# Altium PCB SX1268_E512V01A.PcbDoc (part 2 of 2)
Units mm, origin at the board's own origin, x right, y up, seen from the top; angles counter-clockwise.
Board outline 89 x 58 mm, 2 copper layers (Top Layer, Bottom Layer), stack 0.22 mm thick; 87 components, 53 nets, 246 pads, 1394 vias.
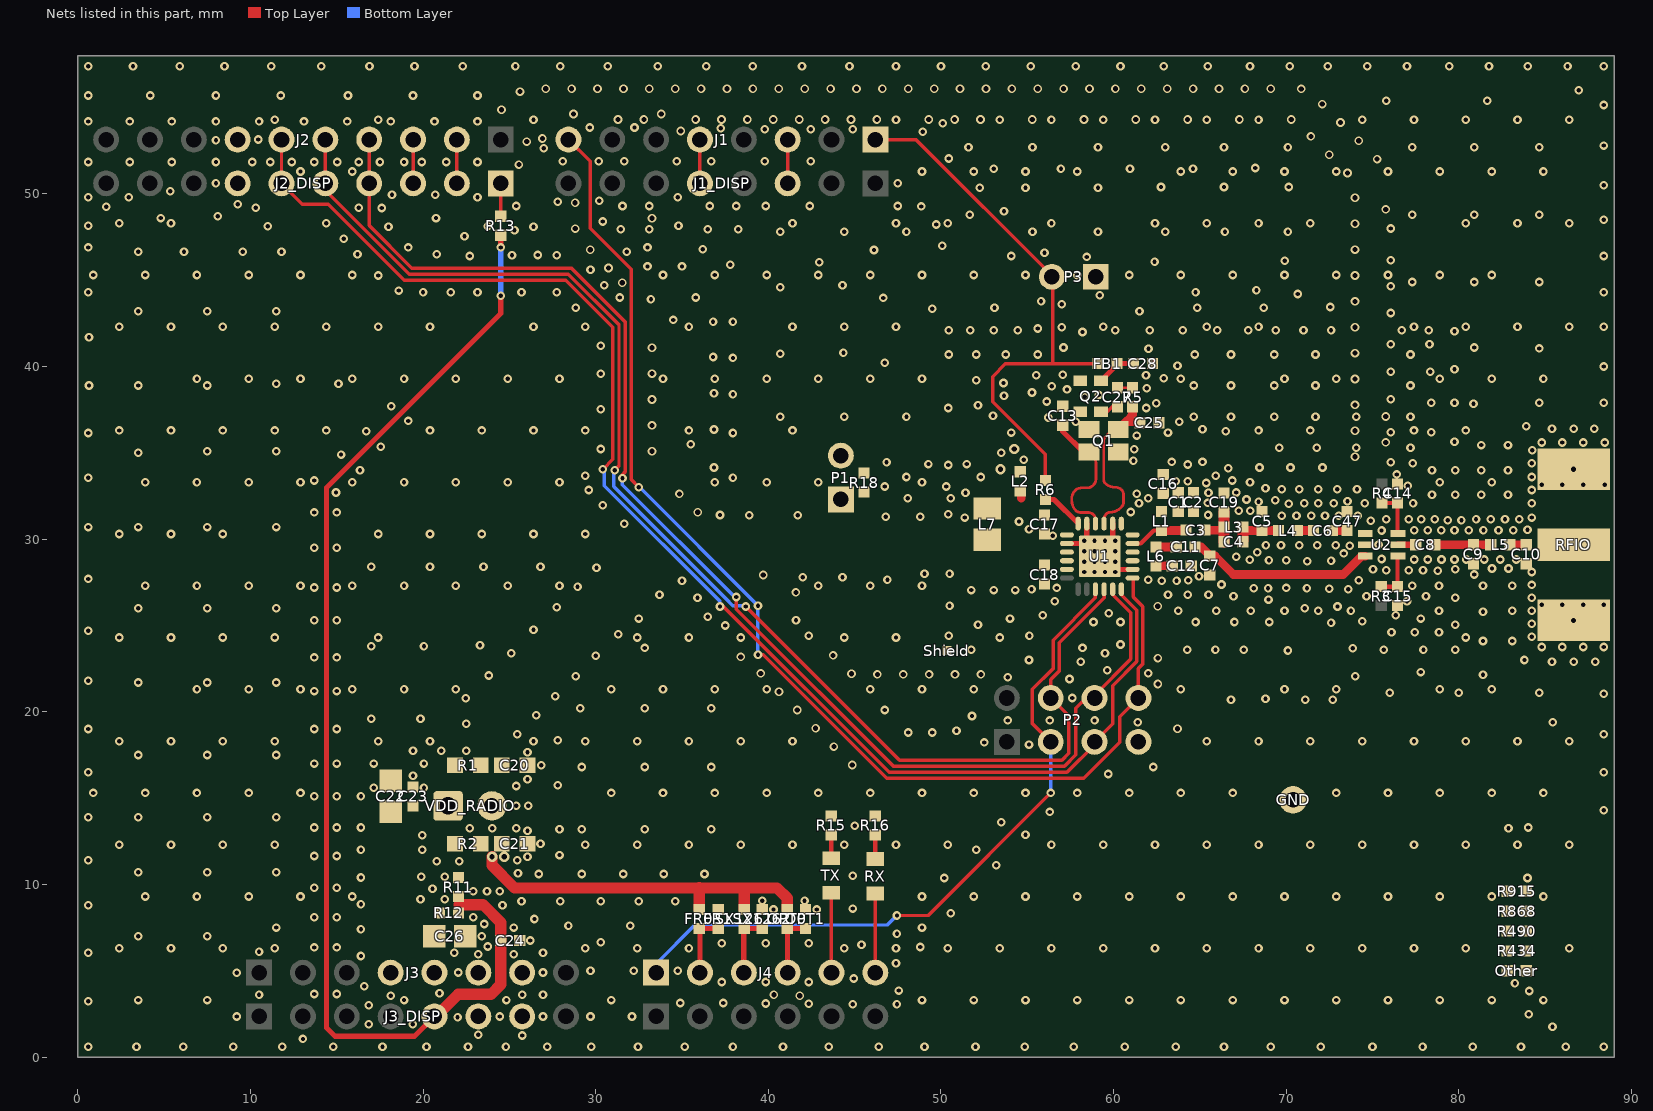
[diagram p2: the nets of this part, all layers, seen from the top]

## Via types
v1: diameter 0.5, hole 0.25, Top Layer to Bottom Layer, tented both sides, 1261 vias
v2: diameter 0.5, hole 0.3, Top Layer to Bottom Layer, tented both sides, 113 vias
v3: diameter 0.5, hole 0.25, Top Layer to Bottom Layer, tented top, 16 vias
v4: diameter 0.6, hole 0.3, Top Layer to Bottom Layer, tented both sides, 4 vias

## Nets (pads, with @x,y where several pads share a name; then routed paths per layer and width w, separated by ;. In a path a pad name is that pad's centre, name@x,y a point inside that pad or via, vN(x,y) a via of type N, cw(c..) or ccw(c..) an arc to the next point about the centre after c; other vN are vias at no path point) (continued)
GND: C1.1 C2.1 C5.1 C7.1 C9.1 C10.1 C12.1 C13.1 C14.2 C15.2 C16.1 C17.1 C18.1 C19.2 C20.1 C21.1 C22.1 C23.1 C24.1 C25.1 C26.1 C28.1 C47.1 FR1.1 GND.1 J2.7 J2_DISP.7 J3.6 J3.7 J3_DISP.6 J3_DISP.7 OPT1.1 Other.1 Other.2 P2.7 P3.1 Q1.2 Q1.4 Q2.1 Q2.2 R15.1 R16.1 R434.1 R434.2 R490.1 R490.2 R868.1 R868.2 R915.1 R915.2 RFIO.2 Shield.1 SX1262.1 U1.2 U1.5 U1.8 U1.20 U1.25 U2.2 | length 4.1
  Top Layer w0.3: U1.8@57.3,29.75 U1.25@58.3,29.75 ; U1.25@58.45,29.85 U1.5@58.45,30.9 ; U1.25@59.95,29.9 U1.2@59.95,30.9 ; U1.25@60.1,28.2 60.15,28.25 U1.20@61.1,28.25
  other v1: 0.6,0.6 3.4,0.6 6.1,0.6 9,0.6 11.85,0.6 14.8,0.6 17.65,0.6 20.2,0.6 22.6,0.6 24.8,0.6 27.2,0.6 29.75,0.6 32.45,0.6 35.15,0.6 37.95,0.6 40.85,0.6 43.5,0.6 46.4,0.6 49.05,0.6 52,0.6 54.85,0.6 57.7,0.6 60.643,0.6 63.6,0.6 66.4,0.6 69.1,0.6 72,0.6 75,0.6 77.9,0.6 80.8,0.6 83.6,0.6 86.2,0.6 88.4,0.6 13.04,1.05 25.75,1.25 23.2,1.3 85.425,1.75 16.85,1.9 19.4,1.9 22,2.3 9.2,2.35 24.45,2.35 26.95,2.35 29.7,2.35 32.1,2.35 84.05,2.475 16.85,3 44.9,3.05 47.45,3.05 39.85,3.1 42.35,3.088 34.9,3.13 37.39,3.13 0.6,3.241 3.5,3.3 7.5,3.3 18.9,3.3 24.829,3.3 30.9,3.3 48.9,3.3 51.9,3.3 54.9,3.3 57.9,3.3 60.9,3.3 63.9,3.3 66.9,3.3 69.9,3.3 72.9,3.3 75.9,3.3 78.9,3.3 81.9,3.3 84.9,3.3 18.125,3.55 10.5,3.6 25.75,3.6 26.95,3.6 13.7,3.65 15,3.65 20.95,3.7 84.075,3.825 47.55,3.85 16.6,4.1 83.25,4.275 37.3,4.35 39.85,4.35 42.35,4.35 44.95,4.55 9.2,4.89 22.035,4.9 26.95,4.9 29.7,5 32.2,5 34.75,5 47.4,5.435 16.4,5.85 23.2,5.95 25.25,5.95 0.6,6.05 21.8,6.05 26.95,6.05 10.5,6.1 2.4,6.3 5.4,6.3 8.4,6.3 11.4,6.3 29.4,6.3 32.4,6.3 35.4,6.3 44.4,6.3 47.4,6.3 50.4,6.3 53.4,6.3 56.4,6.3 59.4,6.3 62.4,6.3 65.4,6.3 68.4,6.3 71.4,6.3 74.4,6.3 77.4,6.3 80.4,6.3 86.4,6.3 13.7,6.35 15,6.35 48.8,6.375 23.75,6.4 45.4,6.5 37.3,6.6 39.85,6.6 42.35,6.6 30.3,6.65 26.2,6.75 3.5,7 7.5,7 23.4,7 47.45,7.15 16.4,7.4 11.5,7.5 25.25,7.5 48.9,7.5 28.42,7.6 32,7.6 23.55,7.709 26.45,8 13.7,8.1 15,8.1 22.9,8.1 50.575,8.325 40.3,8.55 42.8,8.55 44.9,8.6 0.6,8.8 24.6,8.8 16.4,8.85 25.7,9.021 27.95,9.021 30.3,9.021 32.5,9.021 34.6,9.021 39.65,9.05 42.1,9.05 19.85,9.15 21.25,9.15 3.9,9.3 6.9,9.3 9.9,9.3 12.9,9.3 15.9,9.3 48.9,9.3 51.9,9.3 54.9,9.3 57.9,9.3 60.9,9.3 63.9,9.3 66.9,9.3 69.9,9.3 72.9,9.3 75.9,9.3 78.9,9.3 81.9,9.3 84.9,9.3 22.9,9.6 23.7,9.6 24.45,9.6 20.55,9.75 13.7,9.8 15,9.8 50.2,10.375 83.975,10.375 16.4,10.4 19.9,10.45 21.25,10.45 44.9,10.5 26.7,10.6 29.2,10.6 31.6,10.6 33.95,10.6 36.3,10.6 25.5,10.65 3.5,10.7 7.5,10.7 11.5,10.7 53.2,11.11 20.8,11.35 22.1,11.35 0.6,11.4 25.45,11.4 26.05,11.6 13.7,11.65 15,11.65 27.9,11.7 16.4,12 19.95,12 52.05,12 2.4,12.3 5.4,12.3 8.4,12.3 11.4,12.3 29.4,12.3 32.4,12.3 35.4,12.3 38.4,12.3 41.4,12.3 44.4,12.3 47.4,12.3 50.4,12.3 56.4,12.3 59.4,12.3 62.4,12.3 65.4,12.3 68.4,12.3 71.4,12.3 74.4,12.3 77.4,12.3 80.4,12.3 83.4,12.3 86.4,12.3 26.8,12.35 19.95,12.85 54.9,12.871 26.05,13.1 27.9,13.2 29.2,13.2 32.85,13.2 36.7,13.2 22.7,13.25 24,13.25 25.4,13.25 82.875,13.25 13.7,13.3 15,13.3 16.4,13.3 84.025,13.3 45,13.4 53.5,13.6 0.6,13.9 3.5,13.9 7.5,13.9 11.5,13.9 56.3,14.2 88.4,14.3 25.4,14.55 26.1,14.55 13.7,15.1 15,15.1 16.4,15.1 0.9,15.3 3.9,15.3 6.9,15.3 9.9,15.3 12.9,15.3 30.9,15.3 33.9,15.3 36.9,15.3 39.9,15.3 42.9,15.3 45.9,15.3 48.9,15.3 51.9,15.3 54.9,15.3 57.9,15.3 60.9,15.3 63.9,15.3 66.9,15.3 72.9,15.3 75.9,15.3 78.9,15.3 81.9,15.3 84.9,15.3 17.15,15.6 20.05,15.6 25.4,15.7 27.8,15.75 26.05,16.1 19.42,16.3 59.7,16.4 0.6,16.5 88.4,16.5 29.2,16.8 32.85,16.8 36.7,16.8 62.3,16.8 26.85,16.9 13.7,17 15,17 17.15,17 20.05,17 3.5,17.5 7.5,17.5 11.5,17.5 26.05,17.65 19.42,17.75 21.05,17.75 22.5,17.75 55.1,18.1 52.5,18.225 2.4,18.3 5.4,18.3 8.4,18.3 11.4,18.3 17.4,18.3 20.4,18.3 26.4,18.3 29.4,18.3 32.4,18.3 35.4,18.3 38.4,18.3 41.4,18.3 65.4,18.3 68.4,18.3 71.4,18.3 74.4,18.3 77.4,18.3 80.4,18.3 83.4,18.3 86.4,18.3 27.8,18.35 25.45,18.7 88.4,18.7 48.107,18.8 49.5,18.8 50.9,18.9 0.6,19 13.7,19 15,19 22.5,19.3 61.4,19.4 85.45,19.4 53.875,19.5 56.3,19.5 58.9,19.5 17,19.6 19.85,19.6 51.8,19.76 26.55,19.8 46.75,20.104 29.1,20.2 32.85,20.2 36.7,20.2 66.8,20.7 71.1,20.7 72.7,20.7 68.8,20.75 22.477,20.78 57.609,20.8 27.65,20.9 88.4,21.05 76,21.1 80,21.1 84.65,21.1 13.7,21.2 15,21.2 6.9,21.3 9.9,21.3 12.9,21.3 15.9,21.3 18.9,21.3 21.9,21.3 30.9,21.3 33.9,21.3 36.9,21.3 39.9,21.3 45.9,21.3 48.9,21.3 51.9,21.3 63.9,21.3 69.9,21.3 72.9,21.3 78.9,21.3 81.9,21.3 3.5,21.7 7.5,21.7 11.5,21.7 0.6,21.8 57.45,21.9 53.875,22 28.85,22.05 74,22.05 23.8,22.1 81.4,22.15 62,22.225 77.8,22.3 59.625,22.4 58.1,22.9 85.4,22.9 86.65,22.9 87.9,22.9 55.1,23 83.8,23 13.7,23.15 15,23.15 30,23.25 25.1,23.4 59.5,23.4 70.1,23.55 51.75,23.6 64.275,23.6 65.9,23.6 67.55,23.6 75.65,23.6 77.95,23.6 79.8,23.6 73.85,23.675 32.85,23.7 58.2,23.7 84.8,23.75 86,23.75 87.2,23.75 88.4,23.75 17,23.8 20.05,23.8 23.3,23.85 60.4,23.9 81.4,24.1 83.1,24.1 2.4,24.3 5.4,24.3 8.4,24.3 11.4,24.3 17.4,24.3 32.4,24.3 35.4,24.3 38.4,24.3 44.4,24.3 47.4,24.3 53.4,24.3 80.4,24.3 84.225,24.35 42.35,24.4 50.45,24.4 55.125,24.4 31.3,24.5 76.1,24.6 77.45,24.6 78.85,24.6 0.6,24.7 26.4,24.75 37.5,25 52.15,25.05 79.8,25.05 84.225,25.1 72.6,25.15 58.836,25.2 60.4,25.2 64.75,25.2 67,25.2 69.025,25.2 74.4,25.25 13.7,25.3 15,25.3 41.6,25.3 32.5,25.4 54,25.4 77.8,25.4 36.5,25.5 55.9,25.6 76.35,25.6 59.72,25.7 81.4,25.8 63.75,25.85 65.95,25.85 67.95,25.85 69.9,25.85 71.85,25.85 73.75,25.85 78.85,25.85 83.1,25.85 84.225,25.85 3.5,26 7.5,26 11.5,26 71.075,26 27.75,26.05 72.975,26.1 50.5,26.15 84.8,26.2 86,26.2 87.2,26.2 88.4,26.2 56.6,26.4 77,26.4 68.975,26.5 35.9,26.6 79.8,26.6 84.225,26.6 66.95,26.7 74.65,26.7 78.1,26.7 33.7,26.775 63.15,26.775 64.3,26.775 65.5,26.775 51.75,27.05 53.05,27.05 54.3,27.05 55.25,27.1 73.6,27.1 72.5,27.125 68.125,27.15 68.95,27.15 71.2,27.15 56.7,27.175 70,27.175 13.7,27.2 15,27.2 28.95,27.25 3.9,27.3 6.9,27.3 9.9,27.3 12.9,27.3 15.9,27.3 18.9,27.3 21.9,27.3 24.9,27.3 27.9,27.3 42.9,27.3 45.9,27.3 48.9,27.3 77.3,27.3 78.85,27.3 81.4,27.3 83.1,27.3 84.225,27.35 66.25,27.375 35,27.6 62.8,27.6 63.65,27.6 64.325,27.625 74.207,27.625 46.9,27.65 62.016,27.65 0.6,27.696 42,27.8 44.3,27.8 64.95,27.85 80.9,27.95 49.05,28 50.5,28 84.225,28.1 78.775,28.175 75.8,28.2 77.1,28.2 77.925,28.2 75.025,28.25 79.8,28.25 81.925,28.3 82.875,28.3 30.05,28.35 17,28.4 20.4,28.4 23.5,28.4 26.8,28.4 71.225,28.725 72.6,28.75 69,28.775 70,28.775 67.887,28.8 77.425,28.825 78.2,28.825 79,28.825 79.75,28.825 80.425,28.825 81.475,28.825 82.4,28.825 83.325,28.825 75.525,28.85 67.1,28.975 73.325,29.175 68.325,29.25 13.7,29.5 15,29.5 73.675,29.625 68.825,29.65 69.7,29.65 70.75,29.65 71.8,29.65 72.875,29.65 75.35,29.675 56.475,30.2 2.4,30.3 5.4,30.3 8.4,30.3 17.4,30.3 20.4,30.3 23.4,30.3 26.4,30.3 29.4,30.3 75.525,30.5 77.425,30.525 78.2,30.525 78.975,30.525 79.75,30.525 80.575,30.525 81.425,30.525 82.3,30.525 83.15,30.525 83.975,30.55 55.1,30.575 0.6,30.7 3.5,30.7 7.5,30.7 11.5,30.7 31.65,30.9 54.525,31.025 74.9,31.075 79.35,31.1 80.15,31.1 75.8,31.15 77.1,31.15 77.825,31.15 78.6,31.15 81,31.15 81.85,31.15 82.675,31.15 83.5,31.15 51.375,31.25 84.225,31.25 46.8,31.3 48.8,31.3 69.75,31.35 70.6,31.35 71.45,31.35 72.25,31.35 73.05,31.35 74.15,31.35 37.2,31.4 38.9,31.391 41.7,31.391 65.475,31.4 50.425,31.45 13.7,31.55 15,31.55 67.25,31.65 67.925,31.65 30.4,31.97 70.15,32.05 71.05,32.075 71.85,32.075 72.75,32.075 74.55,32.075 77.35,32.075 84.225,32.075 65.45,32.1 68.4,32.175 73.55,32.2 69.375,32.25 67.7,32.3 48.075,32.375 50.575,32.375 78.45,32.575 79.8,32.575 81.3,32.575 82.85,32.575 51.425,32.685 65.5,32.685 14.955,32.7 67.1,32.7 29.6,32.85 84.225,32.85 69.75,32.9 70.75,32.9 71.85,32.9 72.95,32.9 74.1,32.9 68.8,32.95 46.75,33.05 50.3,33.05 77.05,33.1 84.8,33.15 86,33.15 87.2,33.15 88.45,33.15 65.375,33.25 3.9,33.3 6.9,33.3 9.9,33.3 12.9,33.3 15.9,33.3 18.9,33.3 21.9,33.3 24.9,33.3 27.9,33.3 36.9,33.3 39.9,33.3 42.9,33.3 48.9,33.3 67.9,33.3 78.9,33.3 81.9,33.3 63.6,33.35 64.3,33.35 13.7,33.4 66.875,33.4 0.6,33.55 37.95,33.55 48,33.6 52.3,33.6 84.225,33.6 29.4,33.675 65.925,33.675 76.4,33.75 16.35,34 78.45,34 79.8,34 81.3,34 82.85,34 66.65,34.1 36.85,34.15 68.45,34.15 70.25,34.15 72.1,34.15 50.425,34.3 49.275,34.35 51.5,34.35 64.3,34.325 77.325,34.4 84.225,34.4 46.85,34.45 76.05,34.45 63.375,34.475 65.15,34.475 61.15,34.55 15.25,34.9 3.5,35 7.5,35.1 11.5,35.1 84.25,35.15 61.2,35.2 30.3,35.225 69.6,35.3 71.775,35.3 74.05,35.3 77.2,35.3 17.55,35.35 81.3,35.45 82.85,35.45 35.5,35.5 84.8,35.6 86,35.6 87.2,35.6 88.45,35.6 79.75,35.65 61.35,36 0.6,36.15 37.95,36.15 54.075,36.175 63.15,36.175 76.05,36.2 78.4,36.2 16.7,36.25 66.5,36.25 2.4,36.3 5.4,36.3 8.4,36.3 11.4,36.3 14.4,36.3 20.4,36.3 23.4,36.3 26.4,36.3 29.4,36.3 35.4,36.3 41.4,36.3 68.4,36.3 71.4,36.3 77.4,36.3 80.4,36.3 36.85,36.35 65.15,36.375 85.4,36.4 86.65,36.4 87.85,36.4 83.9,36.55 57.8,36.8 63.8,36.8 19.15,36.85 56.225,37.05 40.7,37.1 44.4,37.1 48,37.1 64.65,37.1 66.8,37.1 69.3,37.1 71.7,37.1 74.05,37.1 77.2,37.1 53.015,37.15 30.3,37.531 50.425,37.6 61.9,37.6 18.15,37.7 52.15,37.75 80.85,37.85 62.475,37.875 78.4,37.9 79.75,37.9 84.65,37.9 88.4,37.9 56.125,37.975 76.05,38.1 58.325,38.25 53.65,38.3 59.15,38.35 37.95,38.4 36.85,38.45 55.275,38.5 57.3,38.675 61.925,38.75 56.425,38.85 0.65,38.9 3.5,38.9 7.5,38.9 64.65,38.9 66.8,38.9 69.3,38.9 71.7,38.9 77.2,38.9 11.5,39 15.1,39 53.625,39.05 52.05,39.2 6.9,39.3 9.9,39.3 12.9,39.3 15.9,39.3 18.9,39.3 21.9,39.3 24.9,39.3 27.9,39.3 33.9,39.3 36.9,39.3 39.9,39.3 42.9,39.3 45.9,39.3 48.9,39.3 63.9,39.3 69.9,39.3 72.9,39.3 78.9,39.3 81.9,39.3 84.9,39.3 62.9,39.325 55.525,39.5 61.875,39.5 57.05,39.525 30.3,39.591 76.05,39.7 78.35,39.7 79.75,39.85 88.4,40 63.7,40.05 46.75,40.225 37.95,40.5 36.8,40.55 50.45,40.7 52.05,40.7 53.75,40.7 55.6,40.7 64.7,40.7 66.8,40.7 69.3,40.7 71.7,40.7 77.2,40.7 40.7,40.75 44.35,40.8 62.025,41.025 84.65,41.05 57.1,41.1 80.9,41.1 30.3,41.2 76.05,41.3 78.3,41.3 0.65,41.7 58.2,42 79.75,42.05 50.45,42.1 51.7,42.1 53.05,42.1 54.45,42.1 60.1,42.1 62.1,42.1 64,42.1 66,42.1 67.8,42.1 69.4,42.1 71,42.1 72.6,42.1 76.7,42.1 78.25,42.1 55.6,42.2 2.4,42.3 5.4,42.3 8.4,42.3 11.4,42.3 14.4,42.3 17.4,42.3 20.4,42.3 26.4,42.3 29.4,42.3 35.4,42.3 41.4,42.3 44.4,42.3 47.4,42.3 57,42.276 59.4,42.3 65.4,42.3 68.4,42.3 77.4,42.3 80.4,42.3 83.4,42.3 86.4,42.3 88.4,42.3 36.8,42.6 37.95,42.6 34.5,42.7 76.05,43.1 3.5,43.2 7.5,43.2 11.5,43.2 61.5,43.2 49.5,43.35 28.85,43.4 53.1,43.4 64.85,43.4 68.7,43.4 72.55,43.45 57,43.6 55.8,43.776 33.2,43.9 46.65,43.975 31.4,44 35.8,44 59.2,44.135 70.675,44.2 0.6,44.3 20,44.3 21.6,44.3 23.15,44.3 25.7,44.3 27.75,44.3 64.75,44.3 88.4,44.3 18.6,44.4 68.275,44.425 40.7,44.6 76.05,44.65 30.5,44.7 44.3,44.7 77.3,44.9 80.9,44.9 84.65,44.9 17.4,45.276 0.9,45.3 3.9,45.3 6.9,45.3 9.9,45.3 12.9,45.3 15.9,45.3 33.9,45.3 36.9,45.3 39.9,45.3 42.9,45.3 45.9,45.3 48.9,45.3 51.9,45.3 54.9,45.3 57.9,45.3 60.9,45.3 63.9,45.3 66.9,45.3 69.9,45.3 72.9,45.3 75.9,45.3 78.9,45.3 81.9,45.3 29.7,45.6 33,45.8 35,45.8 37.8,45.9 42.949,46.05 62.375,46.075 69.925,46.125 76.05,46.15 58.45,46.35 22.7,46.4 54.075,46.4 88.4,46.4 25.15,46.45 26.65,46.464 27.75,46.45 16.2,46.5 20.8,46.5 56,46.6 3.5,46.65 6.15,46.65 9.55,46.65 11.8,46.65 31.8,46.65 46.125,46.75 36.199,46.8 0.6,46.9 19.15,46.9 33,46.9 50.075,47 15.4,47.4 22.4,47.546 40.7,47.8 44.4,47.8 48,47.8 55.3,47.8 59.1,47.8 63,47.8 66.45,47.8 70.1,47.8 25.3,47.9 31.45,47.95 33.1,47.95 36.5,47.95 38.25,47.95 76.05,48 18,48.1 26.4,48.1 11,48.125 23.75,48.125 0.6,48.15 34.8,48.15 49.725,48.225 2.4,48.3 5.4,48.3 14.4,48.3 41.4,48.3 47.4,48.3 50.4,48.3 56.4,48.3 62.4,48.3 65.4,48.3 68.4,48.3 71.4,48.3 80.4,48.3 83.4,48.3 86.4,48.3 30.4,48.4 88.4,48.5 4.8,48.6 20.75,48.6 8.1,48.7 51.675,48.8 77.3,48.8 80.9,48.8 84.65,48.8 53.65,49 10.3,49.2 16.275,49.2 17.6,49.187 1.65,49.25 48.85,49.275 25.4,49.3 31.55,49.3 33.1,49.3 36.6,49.3 38.15,49.3 39.85,49.3 42.4,49.3 47.5,49.3 9.26,49.4 27.8,49.55 30.2,49.6 0.6,49.803 2.95,49.803 23.15,49.803 34.75,49.8 18.2,49.95 20.7,49.95 5.35,50.15 52.25,50.35 54.9,50.35 59.1,50.35 62.75,50.4 66.4,50.4 70.15,50.4 88.4,50.5 8,50.61 47.5,50.61 12.9,51.3 15.9,51.3 48.9,51.3 51.9,51.3 54.9,51.3 57.9,51.3 63.9,51.3 66.9,51.3 69.9,51.3 72.9,51.3 75.9,51.3 78.9,51.3 81.9,51.3 84.9,51.3 53.05,51.45 56.95,51.45 60.95,51.45 64.6,51.45 68.2,51.5 0.6,51.85 3,51.85 5.45,51.85 8,51.85 10.1,51.85 11.15,51.85 12.4,51.85 13.7,51.85 15.025,51.85 16.275,51.85 17.5,51.85 18.9,51.85 19.925,51.85 21.35,51.85 23.15,51.85 28.1,51.9 30.18,51.9 31.65,51.9 34.7,51.9 36.7,51.9 39.8,51.9 42.45,51.9 50.45,52.05 27,52.65 51.6,52.7 55.3,52.7 59.1,52.7 63,52.7 66.4,52.7 70.1,52.7 77.3,52.7 80.9,52.7 84.65,52.7 88.4,52.8 8,53.1 10.45,53.15 48.95,53.6 39.8,53.75 42.45,53.75 44.9,53.75 37.25,53.8 29.65,53.85 32.25,53.85 50.1,54.1 0.6,54.2 3,54.2 5.45,54.2 8,54.2 10.5,54.2 13.1,54.2 15.6,54.2 18.12,54.2 20.66,54.2 23.15,54.2 11.4,54.3 17.4,54.3 26.4,54.3 47.4,54.3 53.4,54.3 56.4,54.3 59.4,54.3 62.4,54.3 65.4,54.3 68.4,54.3 74.4,54.3 77.4,54.3 80.4,54.3 83.4,54.3 86.4,54.3 88.4,55.15 75.8,55.4 81.65,55.4 0.6,55.7 4.2,55.7 8,55.7 11.75,55.7 15.65,55.7 19.42,55.7 23.15,55.7 86.95,56 0.6,57.4 3.2,57.4 5.9,57.4 8.5,57.4 11.2,57.4 14.1,57.4 16.9,57.4 19.501,57.4 22.3,57.4 25.35,57.4 27.95,57.4 30.7,57.4 33.6,57.4 36.4,57.4 39.1,57.4 41.95,57.4 44.7,57.4 47.4,57.4 50,57.4 52.6,57.4 55.2,57.4 57.802,57.4 60.4,57.4 62.9,57.4 65.45,57.4 67.9,57.4 70.2,57.4 72.4,57.4 74.7,57.4 77,57.4 79.45,57.4 81.75,57.4 84,57.4 86.3,57.4 88.4,57.4
  other v2: 41.822,3.556 40.323,3.61 44.861,16.922 43.8,17.982 63.7,19.022 42.739,19.043 41.679,20.104 40.618,21.164 62.565,21.611 46.316,22.165 47.816,22.165 49.316,22.165 50.816,22.165 52.316,22.165 44.816,22.207 39.557,22.225 62.565,23.111 38.401,23.181 43.756,23.267 62.563,26.111 41.595,26.917 39.705,27.925 35.908,31.563 34.847,32.624 73.983,34.776 33.265,35.091 75.767,35.604 73.983,36.276 33.265,36.591 75.767,37.104 73.983,37.776 33.265,38.091 73.983,39.276 33.265,39.591 73.983,40.776 33.265,41.091 73.983,42.276 73.983,43.776 31.535,44.858 73.983,45.276 30.743,45.709 29.683,46.769 73.983,46.776 28.812,47.99 73.983,48.276 33.265,48.591 75.767,49.104 28.81,49.49 73.983,49.776 73.551,51.213 25.55,51.7 75.267,52.019 72.491,52.273 26.006,53.029 74.207,53.079 26.914,53.213 71.43,53.334 34.925,53.645 73.146,54.14 31.289,54.308 32.789,54.308 35.789,54.308 37.289,54.308 38.789,54.308 40.289,54.308 41.789,54.308 43.289,54.308 44.789,54.308 46.289,54.308 49.289,54.308 50.789,54.308 52.289,54.308 55.289,54.308 58.289,54.308 61.289,54.308 64.289,54.308 67.289,54.308 70.289,54.308 28.715,54.631 33.795,54.631 24.542,54.878 72.086,55.201 25.617,55.924 27.107,56.092 28.607,56.092 30.107,56.092 31.607,56.092 33.107,56.092 34.607,56.092 36.107,56.092 37.607,56.092 39.107,56.092 40.607,56.092 42.107,56.092 43.607,56.092 45.107,56.092 46.607,56.092 48.107,56.092 49.607,56.092 51.107,56.092 52.607,56.092 54.107,56.092 55.607,56.092 57.107,56.092 58.607,56.092 60.107,56.092 61.607,56.092 63.107,56.092 64.607,56.092 66.107,56.092 67.607,56.092 69.107,56.092 70.874,56.085
  other v3: 58.3,28.1 58.9,28.1 59.5,28.1 60.1,28.1 58.3,28.7 58.9,28.7 59.5,28.7 60.1,28.7 58.3,29.3 58.9,29.3 59.5,29.3 60.1,29.3 58.3,29.9 58.9,29.9 59.5,29.9 60.1,29.9
LED_RX: J4.6 RX.1 | length 4.6
  Top Layer w0.2: RX.1@46.2,9.471 46.2,4.895 J4.6@46.225,4.87
LED_TX: J4.5 TX.1 | length 4.6
  Top Layer w0.2: TX.1@43.65,9.521 43.65,4.935 J4.5@43.66,4.925
MISO: J2.5 J2_DISP.5 P2.4 U1.16 | length 77
  Top Layer w0.2: J2.5@14.34,53.125 J2_DISP.5@14.34,50.61 14.34,50.215 19.205,45.35 28.42,45.35 31.35,42.42 31.35,34.25 v1(31.1,34) ; v1(38.7,26.1) 47.6,17.2 57.01,17.2 57.4,17.59 57.4,19.76 P2.4@56.36,20.8 56.36,21.871 56.85,22.361 56.85,24.003 57.609,24.762 59.45,26.603 U1.16@59.45,27.1
  Bottom Layer w0.2: v1(31.1,34) 31.05,33.95 31.05,33.05 32.13,31.97 37.55,26.55 37.55,26.543 37.943,26.15 38.693,26.15 38.743,26.1 v1(38.7,26.1)
MOSI: J2.4 J2_DISP.4 P2.6 U1.17 | length 77
  Top Layer w0.2: J2.4@16.88,53.15 J2_DISP.4@16.88,50.61 16.88,48.17 19.35,45.7 28.6,45.7 31.7,42.6 31.7,33.893 31.55,33.743 v1(31.55,33.531) ; v1(38.15,26.65) 38.15,25.943 38.493,25.6 38.5,25.6 47.25,16.85 57.155,16.85 57.807,17.502 57.807,20.2 58.407,20.8 P2.6@58.9,20.8 58.9,20.957 61,23.057 61,25.734 59.95,26.784 U1.17@59.95,27.1
  Bottom Layer w0.2: v1(31.55,33.531) 31.55,33.15 38.05,26.65 v1(38.15,26.65)
NetC3_1: C3.1 C4.2 C19.1 L3.1 | length 2.9
  Top Layer w0.25: L3.1@66.4,30.525 66.425,30.525 L3.1@66.45,30.55
  Top Layer w0.5: C3.1@65.3,30.525 L3.1@66.4,30.525
  Top Layer w0.65: C4.2@66.4,29.85 L3.1@66.4,30.525 ; L3.1@66.4,30.55 C19.1@66.4,31.575
NetC3_2: C3.2 L1.1 U1.23 | length 3.4
  Top Layer w0.25: U1.23@61.1,29.75 61.575,29.75 62.325,30.5 L1.1@62.775,30.5
  Top Layer w0.5: L1.1@62.775,30.5 C3.2@64.225,30.5
NetC4_1: C4.1 C5.2 L3.2 L4.1 | length 2.7
  Top Layer w0.25: C4.1@67.5,29.85 C4.1@67.5,29.925
  Top Layer w0.5: L3.2@67.5,30.5 C5.2@68.6,30.5 L4.1@69.55,30.5
  Top Layer w0.65: C4.1@67.5,29.925 L3.2@67.5,30.5
NetC6_1: C6.1 C47.2 U2.1 | length 1.1
  Top Layer w0.25: U2.1@74.375,30.3 U2.1@74.6,30.3
  Top Layer w0.5: C6.1@72.675,30.5 C47.2@73.525,30.5
NetC6_2: C6.2 L4.2 | length 0.9
  Top Layer w0.5: L4.2@70.65,30.5 C6.2@71.575,30.5
NetC7_2: C7.2 C11.1 U2.3 | length 11.2
  Top Layer w0.25: C7.2@65.575,29.025 65.6,29.025 C7.2@65.875,29.025 ; U2.3@74.325,29.025 U2.3@74.575,29.025
  Top Layer w0.5: C11.1@64.725,29.55 65.075,29.55 C7.2@65.6,29.025 ; C7.2@65.875,29.025 66.95,27.95 73.3,27.95 74.351,29.001 U2.3@74.575,29.001
NetC8_1: C8.1 C9.2 L5.1 | length 3.3
  Top Layer w0.5: C8.1@78.6,29.675 80.9,29.675 L5.1@81.85,29.675
NetC8_2: C8.2 U2.5 | length 1
  Top Layer w0.4: U2.5@76.475,29.675 C8.2@77.5,29.675
NetC10_2: C10.2 L5.2 RFIO.1 | length 1
  Top Layer w0.5: L5.2@82.95,29.675 C10.2@83.9,29.675
NetC11_2: C11.2 L6.2 U1.22 | length 1
  Top Layer w0.5: L6.2@62.45,29.55 C11.2@63.4,29.55
NetC12_2: C12.2 L6.1 U1.21 | length 1
  Top Layer w0.5: L6.1@62.45,28.45 C12.2@63.4,28.45
NetC14_1: C14.1 R4.1 U2.6 | length 2.7
  Top Layer w0.25: R4.1@75.55,32.1 C14.1@76.45,32.1 U2.6@76.45,30.325
NetC15_1: C15.1 R3.1 U2.4 | length 2.7
  Top Layer w0.25: R3.1@75.5,27.25 C15.1@76.45,27.25 U2.4@76.45,29.025
NetC16_2: C16.2 L2.2 P1.2 R18.1 U1.1
  other v1: 61,31.575 61.475,32.075 62,32.375 61.35,32.625 54.8,34.6 53.5,35
  other v4: 53.45,34.05 54.25,35.225
NetC17_2: C17.2 L2.1 L7.1 U1.7 | length 0.1
  Top Layer w0.5: L7.1@52.85,31.775 L7.1@52.85,31.8 ; 54.65,32.375 54.65,32.425
NetC27_1: C27.1 Q2.3 | length 1.1
  Top Layer w0.2: Q2.3@59.275,37.375 59.625,37.375 59.925,37.675 C27.1@60.225,37.675 C27.1@60.25,37.675
NetC27_2: C27.2 R5.1 | length 0.9
  Top Layer w0.16: C27.2@60.225,38.775 R5.1@61.1,38.775
NetC28_2: C28.2 FB1.2 Q2.4 | length 2.4
  Top Layer w0.3: Q2.4@59.275,39.175 60.2,40.1 FB1.2@60.2,40.175 C28.2@61.15,40.175 C28.2@61.175,40.175
NetFR0_2: FR0.2 FR1.2 J4.2 | length 3.7
  Top Layer w0.3: J4.2@36,4.94 J4.2@36.04,4.9 ; J4.2@36.04,4.89 J4.2@36.04,4.9 ; J4.2@36.05,4.89 J4.2@36.04,4.9 ; FR1.2@37.1,7.45 FR0.2@36,7.45 36.04,7.41 J4.2@36.04,4.9
NetJ4_3: J4.3 SX1261.2 SX1262.2 | length 3.7
  Top Layer w0.2: J4.3@38.5,4.95 J4.3@38.58,4.87
  Top Layer w0.3: J4.3@38.58,4.89 38.58,7.43 SX1261.2@38.6,7.45 39.63,7.45 SX1262.2@39.65,7.43
NetL7_2: L7.2 U1.9
NetR6_2: R6.2 U1.6 | length 2.3
  Top Layer w0.3: R6.2@56.2,32.3 56.55,32.3 U1.6@57.95,30.9
NetR15_2: R15.2 TX.2 | length 1.3
  Top Layer w0.25: R15.2@43.65,12.871 43.65,11.575 TX.2@43.675,11.55
NetR16_2: R16.2 RX.2 | length 1.4
  Top Layer w0.25: R16.2@46.2,12.871 46.2,11.55 RX.2@46.225,11.525
NSS: J1.8 P2.8 U1.19 | length 69.9
  Top Layer w0.2: J1.8@28.42,53.15 29.675,51.895 29.675,48 32.05,45.625 32.05,33.459 32.5,33.009 v1(32.5,33) ; v1(39.4,23.3) 39.705,23.3 46.855,16.15 58.275,16.15 60.35,18.225 60.35,19.71 P2.8@61.44,20.8 61.44,22.507 61.7,22.767 61.7,22.9 61.7,26 61.7,26.1 61.15,26.65 61.15,27.7 U1.19@61.1,27.75 61.35,27.75 U1.19@61.375,27.725 ; v1(39.4,26.15) v1@39.457,26.15
  Bottom Layer w0.2: v1(32.5,33) 32.55,33 v1(39.4,26.15) v1(39.4,23.3)
OPT: J4.4 OPT0.2 OPT1.2 | length 3.7
  Top Layer w0.3: J4.4@41.12,4.89 41.12,7.43 OPT0.2@41.1,7.45 OPT1.2@42.15,7.45 OPT1.2@42.2,7.45
SCK: J2.6 J2_DISP.6 P2.5 U1.18 | length 81.3
  Top Layer w0.2: J2.6@11.8,53.15 J2_DISP.6@11.8,50.61 13.01,49.4 14.5,49.4 18.9,45 28.275,45 31,42.275 31,34.625 ; v1(30.4,34.055) 30.43,34.055 31,34.625 ; 31,34.7 31,34.625 ; v1(37.2,26.1) 37.4,26.1 47,16.5 57.3,16.5 58.9,18.1 P2.5@58.9,18.26 59.95,19.31 59.95,21.512 61.35,22.912 61.35,25.879 60.45,26.779 U1.18@60.45,27.1
  Bottom Layer w0.2: v1(30.4,34.055) 30.5,33.955 30.5,33.1 37.2,26.4 v1(37.2,26.1)
SD_CS: J2_DISP.1 R13.2 | length 1.9
  Top Layer w0.2: R13.2@24.5,48.7 24.5,50.609 J2_DISP.1@24.5,50.61
SX_NRESET: J4.1 P2.3 U1.15 | length 41.4
  Top Layer w0.2: v1@47.45,8.325 v1(47.45,8.2) 49.26,8.2 v1(56.36,15.3) ; P2.3@56.36,18.26 55.3,19.32 55.3,21.306 56.5,22.506 56.5,24.153 58.95,26.603 U1.15@58.95,27.1
  Bottom Layer w0.2: J4.1@33.5,4.85 J4.1@33.5,4.89 33.5,5.4 35.75,7.65 46.9,7.65 v1(47.45,8.2) ; v1(56.36,15.3) P2.3@56.36,18.26
T_CS: J1.5 J1_DISP.5 | length 2.5
  Top Layer w0.2: J1_DISP.5@36.04,50.61 J1.5@36.04,53.15
T_IRQ: J1.3 J1_DISP.3 | length 2.5
  Top Layer w0.2: J1_DISP.3@41.12,50.61 J1.3@41.12,53.15
TCXO_EN: FB1.1 J1.1 P3.2 R6.1 | length 32.3
  Top Layer w0.2: J1.1@46.2,53.15 48.55,53.15 56.475,45.225 56.475,40.15 ; R6.1@56.05,33.4 56.05,34.909 52.995,37.964 52.995,39.42 53.725,40.15 56.475,40.15 ; FB1.1@59.075,40.175 59.05,40.15 56.475,40.15
TFT_CS: J2.3 J2_DISP.3 | length 2.5
  Top Layer w0.2: J2_DISP.3@19.42,50.61 J2.3@19.42,53.15
TFT_D: J2.2 J2_DISP.2 | length 2.5
  Top Layer w0.2: J2_DISP.2@21.96,50.61 J2.2@21.96,53.15
VDD_3V3: C21.2 FR0.1 OPT0.1 R2.1 R11.1 SX1261.1 | length 21.6
  Top Layer w0.65: v4@23.99,11.6 23.99,11.11 25.3,9.8 36,9.8 ; FR0.1@36,8.55 36,9.8 ; 36,9.81 36,9.8 ; SX1261.1@38.6,8.55 38.6,9.8 ; OPT0.1@41.1,8.55 41.1,9.2 40.5,9.8 38.6,9.8 ; 36,9.8 38.6,9.8
  other v4: 24,11.6 24.7,11.6
VDD_MBED: C22.2 C23.2 J3.4 R1.2 R2.2 VDD_RADIO.1 | length 0
VDD_RADIO: C18.2 C20.2 P1.1 R1.1 R18.2 U1.10 U1.11 VDD_RADIO.2
VDISPLAY: C24.2 J3_DISP.5 R11.2 R12.2 R13.1 | length 68.1
  Top Layer w0.3: J3_DISP.5@20.66,2.35 19.51,1.2 14.9,1.2 14.4,1.7 14.4,32.978 24.5,43.078 24.5,43.6 v1(24.5,44.094) ; v1(24.499,46.9) R13.1@24.5,47.6 R13.1@24.5,47.6
  Top Layer w0.65: J3_DISP.5@20.66,2.35 20.75,2.35 22.035,3.635 23.935,3.635 24.5,4.2 C24.2@24.5,6.75 24.499,7.801 23.475,8.825 22.075,8.825
  Bottom Layer w0.3: v1(24.5,44.094) 24.5,44.4 24.499,44.401 v1(24.499,46.9)
VR_PA: C1.2 C2.2 L1.2 U1.24
VUSB: C26.2 J3.5 R12.1
XTA: C25.2 Q1.3 R5.2 U1.3 | length 9.8
  Top Layer w0.16: U1.3@59.45,30.9 59.45,31.13 cw(c59.938,31.13) 59.593,31.475 59.599,31.482 ; 59.55,31.425 59.609,31.484 cw(c59.8,31.293) 59.8,31.563 ccw(c59.8,32.408) 60.397,31.81 60.478,31.891 ccw(c60.244,32.125) 60.575,32.125 ; Q1.3@60.275,36.35 ccw(c60.275,35.565) 59.72,36.12 59.5,35.9 ccw(c59.681,35.719) 59.425,35.719 59.425,33.466 ccw(c59.766,33.466) 59.525,33.225 ccw(c60.047,33.747) 60.047,33.009 60.107,33.009 cw(c60.107,32.504) 60.464,32.861 cw(c60.197,32.593) 60.575,32.593 60.575,32.141
  Top Layer w0.5: Q1.3@60.275,36.35 60.725,36.8 C25.2@61.525,36.8 ; Q1.3@60.775,36.85 61.1,37.175 R5.2@61.1,37.675
XTB: C13.2 Q1.1 U1.4 | length 8.8
  Top Layer w0.16: 58.1,31.55 58.066,31.55 cw(c58.066,31.891) 58.065,31.55 ; Q1.1@58.724,34.901 Q1.1@58.575,35.05 58.816,34.809 cw(c58.432,34.425) 58.975,34.425 58.975,33.459 cw(c58.552,33.459) 58.851,33.16 58.802,33.11 cw(c58.475,33.438) 58.475,32.975 58.164,32.975 ccw(c58.164,32.424) 57.775,32.814 ccw(c58.257,32.332) 57.575,32.332 57.575,32.254 ccw(c58.429,32.254) 57.825,31.65 ccw(c58.066,31.891) 58.065,31.55 ; U1.4@58.95,30.9 58.95,31.159 ccw(c58.609,31.159) 58.85,31.4 ccw(c58.488,31.038) 58.488,31.55 58.065,31.55
  Top Layer w0.3: C13.2@57.05,36.6 57.05,36.25 58.25,35.05 Q1.1@58.575,35.05
pads on no net: J1.2 J1_DISP.1 J1_DISP.2 J1_DISP.4 J1_DISP.6 J1_DISP.8 J2.8 J2.9 J2.10 J2_DISP.8 J2_DISP.9 J2_DISP.10 J3.1 J3.2 J3.8 J3_DISP.1 J3_DISP.2 J3_DISP.4 J3_DISP.8 J4_DISP.1 J4_DISP.2 J4_DISP.3 J4_DISP.4 J4_DISP.5 J4_DISP.6

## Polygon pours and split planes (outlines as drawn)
GND on Top Layer "Top Layer-No Net 1" (solid, remove dead copper, pour order 142): 0.025,0 0,0.025 0,58 89,58 89,0
NetC6_1 on Top Layer "Top Layer-No Net 1" (solid, remove dead copper, pour order 140): 73.575,30.525 73.575,30.25 74.125,30.25 74.125,30.275 73.875,30.525
NetC12_2 on Top Layer "Top Layer-No Net 1" (solid, remove dead copper, pour order 138): 61,28.6 61.7,28.6 62.15,28.15 62.425,28.15 62.525,28.25 62.525,28.725 62.475,28.775 62.125,28.775 62,28.9 61.05,28.9 61,28.85
NetC11_2 on Top Layer "Top Layer-No Net 1" (solid, remove dead copper, pour order 134): 61,29.4 61.7,29.4 62.1,29.8 62.475,29.8 62.525,29.75 62.525,29.275 62.475,29.225 62.125,29.225 62,29.1 61.05,29.1 61,29.15
NetC6_1 on Top Layer "Top Layer-No Net 1" (solid, remove dead copper, pour order 128): 74.55,30.125 74.025,30.125 73.575,30.575 73.575,30.725 73.95,30.725
NetC3_2 on Top Layer "Top Layer-No Net 1" (solid, remove dead copper, pour order 126): 62.809,30.75 62.325,30.75 61.475,29.9 61.05,29.9 61,29.85 61,29.675 61.575,29.675 62.15,30.25 62.725,30.25 62.875,30.4
NetC16_2 on Top Layer "Top Layer-No Net 1" (solid, remove dead copper, pour order 113): 62.2,33 61.05,33 60.925,32.875 60.925,31.85 61.35,31.85 62.2,32.7
NetL7_2 on Top Layer "Top Layer-No Net 1" (solid, remove dead copper, pour order 45): 52,30.625 52,29.325 52.225,29.1 57.625,29.1 57.7,29.175 57.7,29.35 57.65,29.4 56.65,29.4 56.25,29.8 54.925,29.8 54.1,30.625
NetC16_2 on Top Layer "Top Layer-No Net 1" (solid, remove dead copper, pour order 79): 45.875,33.5 43.925,33.5 43.375,34.05 43.375,35.35 44.6,36.575 52.9,36.575 54.1,35.375 54.1,33.875 53.125,33.875 52.05,34.95 46.325,34.95 45.875,34.5
NetC16_2 on Top Layer "Top Layer-No Net 1" (solid, remove dead copper, pour order 25): 53.025,35.125 53.025,33.975 53.4,33.6 55.475,33.6 55.55,33.675 55.55,34.75 54.725,35.575 53.825,35.575 53.4,35.15 53.05,35.15
NetC17_2 on Top Layer "Top Layer-No Net 1" (solid, pour order 29): 52.05,32.425 52.725,33.1 55.425,33.1 55.425,31.95 55.65,31.725 56.325,31.725 57.667,30.383 57.667,30.167 57.6,30.1 57.025,30.1 57.025,30.45 56.4,31.075 55.675,31.075 55.675,31.141 55.241,31.575 54.15,31.575 53.7,31.125 52.05,31.125
NetC16_2 on Top Layer "Top Layer-No Net 1" (solid, remove dead copper, pour order 49): 60.325,30.908 60.325,31.3 62.025,33 63.192,33 63.192,32.292 62.975,32.075 62.25,32.075 60.75,30.575 60.375,30.575
VDD_RADIO on Top Layer "Top Layer VDD_RADIO" (solid, pour order 6): 22.9,20.55 33.2,30.85 48.571,30.85 48.579,28.45 34.55,28.45 25,18.9 25,18 22.9,18
VDD_RADIO on Top Layer "Top Layer-No Net 1" (solid, remove dead copper, pour order 75): 55.65,28.9 51.975,28.9 50.025,30.85 47.525,30.85 47.525,28.45 50.975,28.45 51.325,28.1 51.375,28.1 56.075,28.1 56.05,28.125 56.05,28.9
VDD_RADIO on Top Layer "Top Layer-No Net 1" (solid, remove dead copper, pour order 77): 45.875,33.05 43.45,33.05 43.45,30.15 44.075,29.525 45.65,29.525 45.875,29.75
GND on Bottom Layer "Top Layer-No Net 1" (solid, remove dead copper, pour order 144): 0,0 88.975,0 88.975,58 0.025,58
NetC16_2 on Bottom Layer "Top Layer-No Net 1" (solid, remove dead copper, pour order 124): 62.3,32.1 62.375,32.175 62.375,32.575 61.9,33.05 60.6,33.05 60.3,32.75 60.3,31.5 61.4,31.5 61.475,31.575
NetC16_2 on Bottom Layer "Top Layer-No Net 1" (solid, remove dead copper, pour order 118): 62.3,33.25 57.625,33.25 56.6,34.275 56.6,34.8 55.75,35.65 53.3,35.65 53.015,35.365 53.015,33.985 53.4,33.6 54.9,33.6 57.6,30.9 61.1,30.9 62.3,32.1

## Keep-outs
Keep-Out Layer:
  lines w0.01: 54.1,37.725 54.1,39.1 cw(c54.5,39.1) 54.9,39.1 ; 54.1,37.747 ccw(c54.954,37.747) 54.35,37.144 56.542,34.952 cw(c56.22,34.63) 56.675,34.63 56.675,34.05 ; 54.9,39.125 54.9,38 ccw(c55.564,38) 55.094,37.531 55.125,37.5 ; 55.1,37.525 57.35,35.275 cw(c57.048,34.973) 57.475,34.973 57.475,34.6 ; 56.675,34.075 ccw(c57.425,34.075) 57.425,33.325 58.283,33.325 60.35,33.325 61.65,33.325 ccw(c61.65,34.075) 62.4,34.075 ; 57.475,34.625 ccw(c57.975,34.625) 57.975,34.125 ; 57.95,34.125 58.283,34.125 60.35,34.125 61.1,34.125 ccw(c61.1,34.625) 61.6,34.625 ; 58.289,31.88 59.875,31.88 ; 58.3,31.88 cw(c58.3,32.28) 58.3,32.68 59.875,32.68 ; 59.85,31.88 ccw(c59.85,32.28) 59.85,32.68 ; 61.6,34.6 61.6,35.45 cw(c61.9,35.45) 61.9,35.75 67.25,35.75 cw(c67.25,35.35) 67.25,34.95 62.7,34.95 ccw(c62.7,34.65) 62.4,34.65 62.4,34.025
  lines w0.3: 0,0 89,0 89,58 0,58 0,0

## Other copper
Top Layer:
  pour cut-out: 62.175,27.866 63.675,27.866 63.675,27.95 62.175,27.95
  pour cut-out: 64.925,28.966 64.075,28.966 63.984,28.875 63.984,28.725 63.925,28.725 63.875,28.775 63.875,29.05 63.9,29.075 64.925,29.075
  pour cut-out: 77.175,29.091 84.127,29.091 84.3,28.918 84.3,28.6 84.5,28.4 84.5,28.775 84.1,29.175 77.175,29.175
  pour cut-out: 77.175,30.259 84.115,30.259 84.291,30.435 84.291,30.768 84.498,30.975 84.525,30.975 84.525,30.784 84.451,30.71 84.451,30.535 84.091,30.175 77.175,30.175
  pour cut-out: 73.9,29.916 73.9,29.95 73.825,30.025 68.12,30.025 68.095,30 68.1,29.995 68.1,29.916
  pour cut-out: 67.35,29.266 66.556,29.266 66.54,29.25 66.54,29.075 66.45,29.075 66.45,29.312 66.488,29.35 67.35,29.35
  pour cut-out: 73.975,31.084 74.275,30.784 74.275,30.775 74.133,30.775 73.933,30.975 68.05,30.975 67.8,31.225 67.8,31.3 67.934,31.3 68.15,31.084
  pour cut-out: 59.725,31.3 59.775,31.35 60.016,31.35 60.025,31.341 60.025,31.205 59.945,31.125 59.725,31.125
  region net NetC10_2: 84.1,30 84.225,30 84.625,30.4 85.1,30.4 85.1,28.95 84.625,28.95 84.225,29.35 84.1,29.35
  pour cut-out: 88.8,26.5 84.5,26.5 84.5,32.85 88.8,32.85
  pour cut-out: 61.758,27.4 61.758,27.792 61.5,28.05 61.5,27.45 61.55,27.4
  region net GND: 75.975,25.55 75.975,26.775 77.1,26.775 77.1,26.275 76.35,26.275 76.35,25.55
  region net GND: 74.563,31.1 68.087,31.1 68.087,32.125 68.487,32.125 68.487,31.675 74.563,31.675
  region net GND: 65.825,31.134 65.825,32.3 68.45,32.3 68.45,32.925 65.15,32.925 65.15,31.134
  region net GND: 63.4,32.913 63.4,32.137 65.431,32.138 65.431,32.913
  region net GND: 68.45,29.9 68.45,29.376 75.425,29.376 75.425,29.9
  region net VR_PA: 61.5,30.25 61.5,30.35 62.425,31.275 64.95,31.275 64.95,31.925 62.325,31.925 60.8,30.4 60.775,30.375 60.775,30.25
  region net GND: 25,7.504 25,5.9 25.3,5.9 25.3,7.5
  region net GND: 22.24,3.145 24.45,3.145 24.45,2.9 22.24,2.9
  region net GND: 60.1,28.4 61.635,28.4 62.305,27.73 62.305,27.625 61.908,27.625 61.483,28.05 60.1,28.05
  region net GND: 16.595,15.3 20.3,15.3 20.3,15.9 19.15,15.9 19.15,16.2 16.595,16.2
  region net VDD_RADIO: 22.9,18.75 25,18.75 25,13.65 22.9,13.65
  region net VDD_3V3: 22.9,10.1 22.9,12.8 25,12.8 25,10.1
  region net VDD_MBED: 22.3,17.35 22.3,11.9 20.45,11.9 20.45,13.25 19.55,13.25 19.25,12.95 19.25,15.15 20.45,15.15 20.45,17.35
  region net VDD_MBED: 17.4,4 18.85,4 19.45,4.6 19.45,15.15 16.85,15.15 16.85,4.55
  region net GND: 55.65,30.65 55.65,29.95 56.425,29.95 56.8,29.575 58.3,29.575 58.3,29.95 56.925,29.95 56.75,30.125 56.75,30.425 56.525,30.65
  pour cut-out: 60.586,27.675 60.542,27.675 57.8,27.675 57.802,27.544 60.586,27.544
  pour cut-out: 60.586,27.625 60.45,27.625 60.45,30.325 57.775,30.325 57.775,30.449 60.58,30.452 60.582,30.45
  pour cut-out: 57.925,30.425 57.925,27.65 57.775,27.65 57.775,30.425
  region net VDISPLAY: 21.7,9.65 21.7,8 22.4,8 22.4,9.65
  region net VUSB: 19.95,8.7 19.95,4.89 21.35,4.89 21.35,8.7
  region net GND: 21.5,7.85 21.5,6.1 22.45,6.1 22.45,7.4 23.45,7.4 23.45,7.85
  region net VDD_3V3: 21.7,10.75 21.7,10.05 25,10.05 25,10.75
  pour cut-out: 21.474,8.875 21.549,8.95 21.549,10.876 21.55,10.9 22.8,10.901 22.8,10.8 21.65,10.8 21.65,8.8 19.55,8.8 19.55,8.875
  pour cut-out: 22.6,9.95 22.6,7.85 22.4,7.85 22.4,9.95
  region net GND: 22.15,4.11 23.69,4.11 24.02,4.44 24.02,5.8 23.711,5.8 23.711,4.379 22.15,4.379
  region net GND: 24.975,3.635 24.975,7.4 25.2,7.4 25.2,3.635
  region net VDD_RADIO: 55.65,28.1 57.3,28.1 57.3,28.4 57,28.4 56.95,28.45 56.95,28.55 57,28.6 57.3,28.6 57.3,28.9 55.65,28.9
  region net GND: 55.04,27.241 55.749,27.95 56.75,27.95 56.75,27.725 56.7,27.675 55.875,27.675 55.725,27.525 55.725,27.2 55.04,27.2
  region net GND: 76.025,33.95 76.55,33.95 76.55,33.2 77.05,33.2 77.05,32.575 76.025,32.575
  region net GND: 36.475,9.325 36.475,8.225 37.425,8.225 37.425,9.325
  region net GND: 39.075,9.325 39.075,8.225 39.975,8.225 39.975,9.325
  region net GND: 41.575,9.65 41.575,8.225 42.47,8.225 42.47,9.65
Bottom Layer:
  region net VDD_3V3: 23.65,11.95 23.65,11.25 25.029,11.25 25.029,11.95
  region net GND: 57.75,30.4 57.75,27.6 60.65,27.6 60.65,30.4

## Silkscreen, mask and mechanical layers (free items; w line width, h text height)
Top Overlay:
  lines w0.15: 77.2,29 77.2,25.55 51.45,25.55 51.45,40.675 77.2,40.675 77.2,30.35
  text "1" at 25,56.55 h1
  text "SX1268 Evaluation Board" at 50.2,55.1 h1.4
  text "J2" at 25.2,54.9 h1.27
  text "J1" at 45.8,54.9 h1.27
  text "1" at 47.511,52.71 h1
  text "1" at 26,52.61 h1
  text "PCB_E512V01A" at 56.65,52.55 h1.27
  text "SX1268" at 66.075,37.2 h1.4
  text "DIO1" at 51,14.7 h1
  text "MI" at 55.6,14.7 h1
  text "MO" at 58.091,14.7 h1
  text "NSS" at 61.236,14.7 h1
  text "BUSY" at 50.9,13.1 h1
  text "NR" at 55.525,13.1 h1
  text "SCK" at 57.913,13.1 h1
  text "GND" at 61.215,13.1 h1
  text "Freq Band:" at 75.2,11.9 h1.27
  text "J3" at 9.524,6.85 h1.27
  text "J4" at 32.45,6.85 h1.27
  text "1" at 8.911,4.41 h1
  text "1" at 31.731,4.415 h1
Bottom Overlay:
  text "RoHS" at 16.594,26.42 h2.2 r270
  text "compliant" at 15.044,24.37 h2.2 r270
  text "PCB_E512V01A" at 2,17.9 h1.27 r270
Bottom Solder:
  region: 57.9,30.3 57.9,27.7 60.5,27.7 60.5,30.3
Mechanical 1:
  lines w0.01: 54.1,37.725 54.1,39.1 cw(c54.5,39.1) 54.9,39.1 ; 54.1,37.75 54.1,37.747 ccw(c54.954,37.747) 54.35,37.144 56.542,34.952 cw(c56.22,34.63) 56.675,34.63 56.675,34.6 56.675,34.05 ; 54.9,39.125 54.9,38 ccw(c55.564,38) 55.094,37.531 55.125,37.5 57.338,35.288 ; 56.675,34.075 ccw(c57.425,34.075) 57.425,33.325 58.275,33.325 ; 57.337,35.288 57.35,35.275 cw(c57.048,34.973) 57.475,34.973 57.475,34.962 57.475,34.625 ccw(c57.975,34.625) 57.975,34.125 ; 57.95,34.125 58.275,34.125 ; 58.25,33.325 ccw(c58.25,33.725) 58.25,34.125 ; 58.289,31.88 59.875,31.88 ; 58.3,31.88 cw(c58.3,32.28) 58.3,32.68 59.875,32.68 ; 59.85,31.88 ccw(c59.85,32.28) 59.85,32.68 ; 61.6,34.6 61.6,35.45 cw(c61.9,35.45) 61.9,35.75 67.25,35.75 cw(c67.25,35.35) 67.25,34.95 62.7,34.95 ccw(c62.7,34.65) 62.4,34.65 62.4,34.025 ; 61.6,34.625 cw(c61.1,34.625) 61.1,34.125 60.35,34.125 ccw(c60.35,33.725) 60.35,33.325 61.65,33.325 ccw(c61.65,34.075) 62.4,34.075 ; 54,39 54,39
  lines w0.05: 0,0 89,0 89,58 0,58 0,0
Mechanical 3:
  text "Origin(0;0)" at -9.95,-2.35 h1

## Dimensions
0,0 to 0,58 on Mechanical 3
0,0 to 89,0 on Mechanical 3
